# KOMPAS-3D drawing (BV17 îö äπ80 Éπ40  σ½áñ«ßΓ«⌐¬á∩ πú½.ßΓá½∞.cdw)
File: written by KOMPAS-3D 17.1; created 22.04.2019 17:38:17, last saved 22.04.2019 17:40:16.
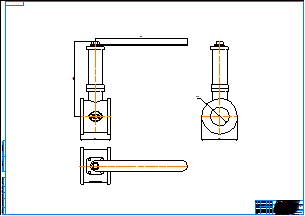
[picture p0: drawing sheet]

Sheet 1: A0, landscape

Title block, sheet 1: name: BV17 МФ Ду80 Ру40 / хладостойкая угл.сталь; material: Внимание! Данный продукт является объектом авторского права ООО «Торговый Дом АДЛ». / Запрещается изменение, копирование, распространение / (в том числе путем копирования на другие сайты и ресурсы в Интернете) / или любое иное использование информации и объектов без предварительного / согласия правообладателя (ООО «Торговый Дом АДЛ»).; mass: 13,65; sheets: 1; organisation: ООО "Торговый дом АДЛ"; sheet format: A0; stored path: \\adlc.lan\data\АДЛ_ПКД\3D-модели\ADL production\Краны шаровые серии BV\BV17 МФ хладостойкая угл.сталь Ру40\KOMPAS 2D\BV17 МФ Ду80 Ру40  хладостойкая угл.сталь.cdw

Views: Вид 1, Проекционный вид 2, Проекционный вид 3
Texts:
  user
Dimensions and other numbers on the sheet: 360; 292; 120; 142; 76; 1:1; 1; 13,65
